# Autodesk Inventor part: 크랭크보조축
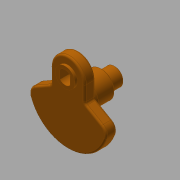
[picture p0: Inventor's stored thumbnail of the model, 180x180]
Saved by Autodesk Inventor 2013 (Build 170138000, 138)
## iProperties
Created: 2016-11
Part Number: 크랭크보조축
Material: 강철, 탄소
Document SubType Name: Modeling
Designer: mduedu
Density: 1 g/cm^3
Author: mduedu
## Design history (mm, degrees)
sketch "스케치1" dims "d8" = 65
  geometry: L1 (-19, 26.368)-(-19, 8.368); L2 (-19, 8.368)-(-44.545, -6.381); L3 (0, 26.368)-(0, -45); L4 (19, 26.368)-(19, 8.368); L5 (19, 8.368)-(44.545, -6.381); C1 r 10 at (0, 0); C2 r 17.5 at (0, 0); A1 r 45 centre (0, 0) between (-44.545, -6.381) and (0, -45); A2 r 19 centre (0, 26.368) between (0, 45.368) and (-19, 26.368); A3 r 19 centre (0, 26.368) between (19, 26.368) and (0, 45.368); A4 r 45 centre (0, 0) between (0, -45) and (44.545, -6.381); 2 further points
  constraints: 10 end point, 8 point on circle, 6 centre point, 4 coincident, 3 symmetric about line, 2 point on line, 1 parallel, 1 tangent, 1 vertical, 1 vertical alignment, 5 other
  dimensions: "d1" = 20 diameter of C1; "d2" = 35 diameter of C2; "d4" = 18 distance of L1.start L1.end; "d5" = 120 deg angle of L2 L1; "d6" = 45 radius of A1; "d9" = 19 radius of A2
extrude "돌출1" new body sketch "스케치1" distance "d10" = 12; taper "d11" = 0 deg
sketch "스케치2"
  geometry: C1 r 7.5 at (0, 26.368); C2 r 11 at (0, 26.368); A1 r 19 centre (0, 26.368) between (19, 26.368) and (-19, 26.368) reference; 1 further point
  constraints: 2 centre point, 2 coincident
  dimensions: "d16" = 15 diameter of C1; "d17" = 22 diameter of C2
extrude "돌출10" join sketch "스케치1" distance "d46" = 5; taper "d47" = 0 deg
extrude "돌출11" join sketch "스케치1" distance "d48" = 41; taper "d49" = 0 deg
extrude "돌출12" join sketch "스케치2" distance "d50" = 3; taper "d51" = 0 deg
extrude "돌출13" cut sketch "스케치2" stored distance "d52" = 3; taper "d53" = 0 deg
sketch "스케치7"
  geometry: L1 (5.75, -4.815)-(-5.75, -4.815); L2 (-5.75, -4.815)-(-5.75, 4.815); L3 (-5.75, 4.815)-(5.75, 4.815); L4 (5.75, 4.815)-(5.75, -4.815); L5 (5.75, -4.815)-(-5.75, 4.815); L6 (-5.75, -4.815)-(5.75, 4.815); A1 r 7.5 centre (0, 0) between (-5.75, 4.815) and (-5.75, -4.815); A2 r 7.5 centre (0, 0) between (5.75, -4.815) and (5.75, 4.815); 2 further points
  constraints: 12 end point, 4 point on circle, 2 centre point, 2 midpoint, 2 parallel, 1 coincident, 1 horizontal, 1 perpendicular, 2 other
  dimensions: "d54" = 11.5 distance of L2.end L3.end
extrude "돌출14" join sketch "스케치7" stored distance "d56" = 40.75; taper "d57" = 0 deg
sketch "스케치8"
  geometry: C1 r 17.5 at (0, 0) reference; C2 r 15 at (0, 0); 1 further point
  constraints: 1 centre point, 1 coincident
  dimensions: "d58" = 30 diameter of C2
extrude "돌출15" join sketch "스케치8" distance "d59" = 21; taper "d60" = 0 deg
chamfer "모따기3" distance "d61" = 1; stored, may be unused: second distance "d62" = 2, angle "d63" = 45 deg
fillet "모깎기3" dims "d64" = 3, "d65" = 10
fillet "모깎기4" dims "d66" = 2
node "솔리드1"
other parameters: "d3" = 38
